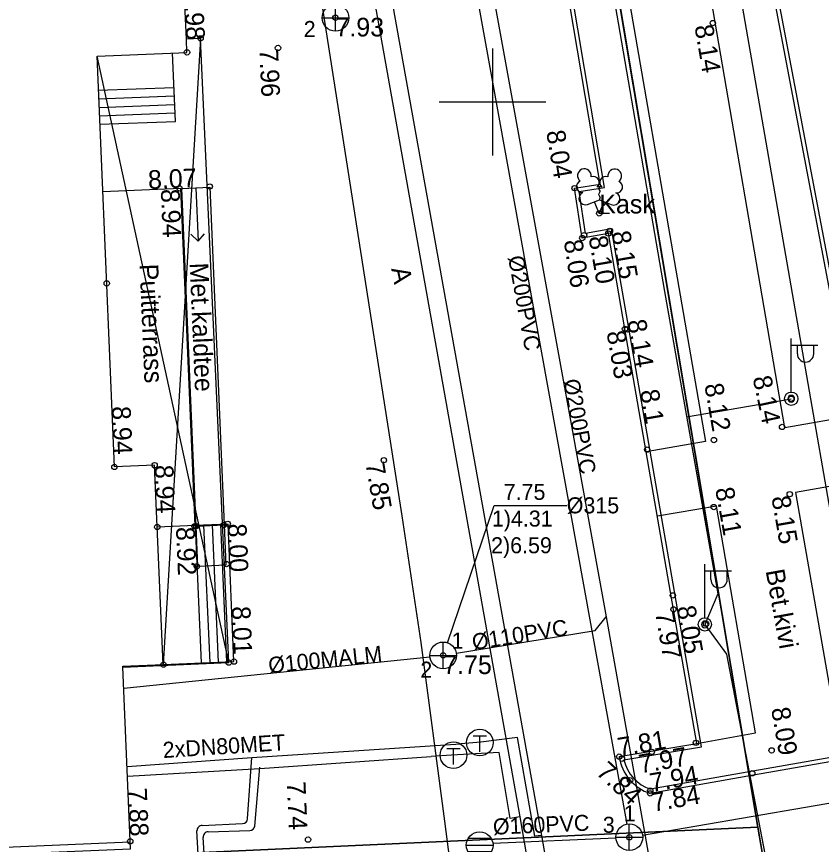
# Model space of a CAD drawing. Extents: x 473307 to 473719, y 6532843 to 6533381.
# Drawn here: x 473582.18 to 473612.32, y 6533222.19 to 6533253.2 of the extents above; entities that cross this region are included whole.
import ezdxf

# ---------------------------------------------------------------- set-up
doc = ezdxf.new("R2010")
doc.units = 0
for name, color, linetype in [('Default', 7, 'Continuous'), ('HOONE', 7, 'Continuous'), ('HOONEDET', 7, 'Continuous'), ('KKAEV', 7, 'Continuous'), ('KKAEV_NR', 7, 'Continuous'), ('KORGUS', 7, 'Continuous'), ('KPKAABEL', 7, 'Continuous'), ('KTRASS', 7, 'Continuous'), ('KTRASS_TEKST', 7, 'Continuous'), ('MPKAABEL', 7, 'Continuous'), ('PIIR', 7, 'Continuous'), ('POST', 7, 'Continuous'), ('PUU', 7, 'Continuous'), ('SITRASS', 7, 'Continuous'), ('SKKAEV', 7, 'Continuous'), ('SKKAEV_NR', 7, 'Continuous'), ('SKTRASS', 7, 'Continuous'), ('SKTRASS_TEKST', 7, 'Continuous'), ('TEE', 7, 'Continuous'), ('TKAEV', 7, 'Continuous'), ('TTRASS', 7, 'Continuous'), ('TTRASS_TEKST', 7, 'Continuous'), ('VORK', 7, 'Continuous')]:
    doc.layers.add(name, color=color, linetype=linetype)

# ---------------------------------------------------------------- blocks, each defined once
blk = doc.blocks.new('KAKAEV')
at = {"layer": 'Default'}
for p, q in [((0, -1), (0, 1)), ((-1, 0), (1, 0))]:
    blk.add_line(p, q, dxfattribs=at)
blk.add_circle((0, 0), 1, dxfattribs=at)
blk = doc.blocks.new('REKAEV')
at = {"layer": 'Default'}
for p, q in [((-1, 0), (1, 0)), ((0.86, 0.5), (-0.86, 0.5)), ((0.86, -0.5), (-0.86, -0.5))]:
    blk.add_line(p, q, dxfattribs=at)
blk.add_circle((0, 0), 1, dxfattribs=at)
blk = doc.blocks.new('LEHTP2')
at = {"layer": 'Default'}
for p, q in [((-0.88, 0.67), (0.01, 1.02)), ((0, 0), (-0.35, 0.88)), ((0, 0), (0.36, 0.88)), ((0.01, 1.02), (0.89, 0.66)), ((0.76, 0), (0, 0))]:
    blk.add_line(p, q, dxfattribs=at)
blk.add_lwpolyline([(0.01, 2.01), (-0.03, 1.86), (-0.03, 1.82), (-0.01, 1.76), (0.03, 1.69), (0.04, 1.65), (0.01, 1.58), (-0.04, 1.48), (-0.05, 1.43), (-0.04, 1.4), (-0.02, 1.34), (0.05, 1.22), (0.06, 1.18), (0.05, 1.14), (0.02, 1.07), (0.01, 1.02)], dxfattribs=at)
for centre, radius, start, end in [((-1.114, 2.828), 0.512, 111.50269, 232.51731), ((-1.114, 2.828), 0.512, 350.48556, 111.50017), ((1.158, 2.811), 0.512, 67.6168, 188.63142), ((1.158, 2.811), 0.512, 306.59966, 67.61428), ((-0.445, 2.327), 0.448, 308.50412, 111.57247), ((0.481, 2.318), 0.45, 67.7016, 230.51262), ((-1.262, 2.005), 0.448, 111.43041, 274.49868), ((0.008, 1.535), 0.475, 66.76552, 111.50149), ((1.293, 1.986), 0.448, 264.6183, 67.68657), ((-1.053, 1.117), 0.475, 111.50143, 291.50036), ((1.07, 1.101), 0.475, 247.61661, 67.61554)]:
    blk.add_arc(centre, radius, start, end, dxfattribs=at)
blk = doc.blocks.new('MEPOST')
at = {"layer": 'Default'}
blk.add_circle((0, 0), 0.5, dxfattribs=at)
for start, end in [(0, 180), (180, 0)]:
    blk.add_arc((0, 0), 0.25, start, end, dxfattribs=at)
blk = doc.blocks.new('VAPOST')
at = {"layer": 'Default'}
for p, q in [((0, 0.5), (0, 4.5)), ((0, 4), (2, 4)), ((0.453, 3.358), (0.453, 4)), ((1.679, 3.358), (1.679, 4))]:
    blk.add_line(p, q, dxfattribs=at)
blk.add_arc((1.066, 3.358), 0.613, 180, 0, dxfattribs=at)
blk = doc.blocks.new('SOKAEV')
at = {"layer": 'Default'}
for p, q in [((-0.5, 0.5), (0.5, 0.5)), ((0, -0.7), (0, 0.5))]:
    blk.add_line(p, q, dxfattribs=at)
blk.add_circle((0, 0), 1, dxfattribs=at)
blk = doc.blocks.new('VKORIS')
at = {"layer": 'Default'}
for p, q in [((0, 4), (0, -4)), ((-4, 0), (4, 0))]:
    blk.add_line(p, q, dxfattribs=at)

msp = doc.modelspace()

# ---------------------------------------------------------------- linework, layer by layer
at = {"layer": 'HOONE'}
for points in [[(473586.451, 6533222.028), (473586.163, 6533228.83), (473590.126, 6533228.998), (473589.07, 6533252.381), (473588.538, 6533252.355), (473587.928, 6533265.086), (473574.864, 6533264.513), (473574.621, 6533270.17), (473553.465, 6533269.148), (473553.468, 6533269.088), (473497.143, 6533266.366), (473498.091, 6533246.719), (473499.996, 6533208.142), (473556.654, 6533210.892), (473555.213, 6533238.366), (473566.97, 6533238.94), (473567.826, 6533221.491), (473567.7, 6533221.486), (473567.712, 6533221.234), (473586.451, 6533222.028)], [(473586.163, 6533228.83), (473586.161, 6533228.861), (473587.666, 6533228.924), (473587.35, 6533236.393), (473585.845, 6533236.33), (473585.193, 6533251.717), (473588.562, 6533251.859), (473588.538, 6533252.355)]]:
    msp.add_lwpolyline(points, dxfattribs=at)
at = {"layer": 'HOONEDET'}
for p, q in [((473585.247, 6533250.436), (473588.072, 6533250.546)), ((473585.26, 6533250.118), (473588.085, 6533250.228)), ((473585.272, 6533249.799), (473588.097, 6533249.91)), ((473585.285, 6533249.481), (473588.11, 6533249.592)), ((473588.891, 6533246.787), (473588.976, 6533244.781)), ((473588.976, 6533244.781), (473588.706, 6533245.043)), ((473588.976, 6533244.781), (473589.223, 6533245.065)), ((473588.905, 6533234.111), (473589.95, 6533234.155)), ((473589.183, 6533234.151), (473589.412, 6533228.998)), ((473589.499, 6533234.164), (473589.728, 6533229.011)), ((473589.814, 6533234.178), (473590.043, 6533229.025)), ((473588.868, 6533234.138), (473589.097, 6533228.985)), ((473567.826, 6533221.491), (473586.44, 6533222.28))]:
    msp.add_line(p, q, dxfattribs=at)
for points in [[(473589.07, 6533252.381), (473587.666, 6533228.924)], [(473585.301, 6533249.163), (473588.126, 6533249.274), (473588.018, 6533251.836)], [(473590.126, 6533228.998), (473585.193, 6533251.717)], [(473588.868, 6533234.138), (473588.333, 6533246.763), (473585.408, 6533246.639)], [(473588.369, 6533246.764), (473589.414, 6533246.809), (473589.95, 6533234.155), (473590.013, 6533232.649), (473588.969, 6533232.605), (473588.905, 6533234.111), (473588.369, 6533246.764)], [(473587.666, 6533228.924), (473590.322, 6533229.036), (473590.104, 6533234.19), (473588.868, 6533234.138), (473587.448, 6533234.078)]]:
    msp.add_lwpolyline(points, dxfattribs=at)
at = {"layer": 'KKAEV_NR'}
msp.add_lwpolyline([(473598.317, 6533229.744), (473600.062, 6533234.89), (473602.783, 6533234.89)], dxfattribs=at)
at = {"layer": 'KORGUS'}
for centre in [(473594.121, 6533253.154), (473608.254, 6533252.957), (473589.07, 6533252.381), (473588.562, 6533251.859), (473591.97, 6533252.023), (473588.28, 6533246.761), (473589.413, 6533246.834), (473603.078, 6533246.77), (473604.002, 6533245.825), (473603.363, 6533244.901), (473603.434, 6533245.011), (473604.341, 6533245.074), (473604.4, 6533245.173), (473585.554, 6533243.205), (473604.961, 6533241.496), (473605.041, 6533241.48), (473611.192, 6533238.885), (473610.847, 6533237.827), (473608.293, 6533237.337), (473605.794, 6533236.978), (473595.933, 6533236.582), (473585.845, 6533236.33), (473587.35, 6533236.393), (473611.136, 6533235.31), (473608.289, 6533234.825), (473587.448, 6533234.078), (473588.848, 6533234.1), (473588.905, 6533234.109), (473589.939, 6533234.155), (473590.089, 6533234.196), (473588.931, 6533232.603), (473590.044, 6533232.689), (473606.757, 6533231.515), (473606.781, 6533230.992), (473607.999, 6533230.452), (473598.156, 6533229.27), (473587.683, 6533228.925), (473590.126, 6533228.998), (473590.322, 6533229.036), (473607.62, 6533225.995), (473610.457, 6533225.711), (473604.75, 6533225.478), (473604.85, 6533225.397), (473605.971, 6533225.655), (473609.729, 6533224.853), (473605.155, 6533224.589), (473605.912, 6533224.206), (473605.907, 6533224.098), (473586.438, 6533222.308), (473593.094, 6533222.367), (473605.127, 6533222.457)]:
    msp.add_circle(centre, 0.1, dxfattribs=at)
at = {"layer": 'KPKAABEL'}
msp.add_lwpolyline([(473599.245, 6533215.151), (473598.214, 6533223.062), (473597.334, 6533229.753), (473596.618, 6533234.501), (473594.535, 6533247.835), (473592.795, 6533258.945), (473591.16, 6533268.89), (473578.283, 6533269.448)], dxfattribs=at)
at = {"layer": 'KTRASS'}
for points in [[(473596.379, 6533274.552), (473599.595, 6533256.427), (473604.261, 6533230.713), (473605.956, 6533221.161)], [(473598.649, 6533229.351), (473603.845, 6533230.204), (473604.259, 6533230.711)], [(473586.196, 6533228.038), (473597.659, 6533229.219)]]:
    msp.add_lwpolyline(points, dxfattribs=at)
at = {"layer": 'MPKAABEL'}
for points in [[(473525.948, 6533290.824), (473539.287, 6533291.718), (473545.145, 6533292.046), (473550.656, 6533292.727), (473564.851, 6533292.918), (473566.45, 6533292.671), (473568.205, 6533285.94), (473572.537, 6533278.089), (473573.477, 6533277.469), (473574.937, 6533277.378), (473588.904, 6533277.934), (473598.263, 6533278.206), (473600.541, 6533275.557), (473602.095, 6533267.853), (473603.802, 6533258.2), (473603.216, 6533257.059), (473604.096, 6533256.527), (473606.448, 6533242.906), (473608.439, 6533231.57), (473607.954, 6533230.431), (473608.769, 6533229.316), (473610.682, 6533219.295)], [(473603.216, 6533257.059), (473604.096, 6533256.527), (473606.448, 6533242.906), (473608.439, 6533231.57), (473607.954, 6533230.431)], [(473607.273, 6533238.211), (473611.192, 6533238.885)], [(473607.954, 6533230.431), (473608.769, 6533229.316), (473610.682, 6533219.295), (473613.1, 6533204.928), (473612.486, 6533203.753)]]:
    msp.add_lwpolyline(points, dxfattribs=at)
at = {"layer": 'PIIR'}
msp.add_lwpolyline([(473678.608, 6532842.593), (473677.66, 6532847.73), (473668.24, 6532906.4), (473664.64, 6532927.81), (473654.16, 6532926.37), (473630.89, 6533065.72), (473641.36, 6533067.51), (473636.3, 6533097.55), (473618.8, 6533170.64), (473609.94, 6533222.84), (473601.54, 6533272.81), (473599.09, 6533295.91), (473592.3, 6533328.43), (473587.14, 6533353.72), (473584.47, 6533353.28), (473580.56, 6533374.06), (473585.23, 6533374.14), (473584.699, 6533380.885)], dxfattribs=at)
for points in [[(473586.5, 6533271.93), (473601.56, 6533272.81), (473609.94, 6533222.84), (473586.39, 6533221.76), (473567.96, 6533221.17), (473565.61, 6533263.9), (473587.68, 6533264.9)], [(473558.63, 6533220.73), (473567.96, 6533221.17), (473586.39, 6533221.76), (473609.94, 6533222.84), (473618.8, 6533170.64), (473601.75, 6533167.04), (473561.43, 6533165.2), (473559.2, 6533209.37)]]:
    msp.add_lwpolyline(points, close=True, dxfattribs=at)
at = {"layer": 'SITRASS'}
msp.add_lwpolyline([(473619.598, 6533194.755), (473606.651, 6533269.171)], dxfattribs=at)
at = {"layer": 'SKKAEV_NR'}
msp.add_lwpolyline([(473605.62, 6533222.541), (473615.79, 6533224.289), (473619.645, 6533224.289)], dxfattribs=at)
at = {"layer": 'SKTRASS'}
msp.add_line((473595.936, 6533273.237), (473605.038, 6533222.949), dxfattribs=at)
msp.add_lwpolyline([(473600.016, 6533222.238), (473604.627, 6533222.435)], dxfattribs=at)
at = {"layer": 'TEE'}
for points in [[(473606.081, 6533277.468), (473606.665, 6533274.345), (473613.506, 6533238.237), (473615.579, 6533226.633)], [(473606.226, 6533277.506), (473606.812, 6533274.373), (473613.654, 6533238.264), (473613.654, 6533238.264), (473615.735, 6533226.614)], [(473592.376, 6533275.568), (473601.305, 6533275.875), (473607.974, 6533237.28), (473605.758, 6533236.896)], [(473604.75, 6533225.478), (473607.651, 6533225.971), (473606.781, 6533230.992), (473605.758, 6533236.896), (473604.961, 6533241.496), (473604.341, 6533245.074), (473603.363, 6533244.901), (473603.078, 6533246.77), (473604.03, 6533246.923), (473602.054, 6533258.671), (473599.216, 6533274.876), (473594.157, 6533274.026)], [(473604.925, 6533225.356), (473607.824, 6533225.848), (473606.929, 6533231.017), (473605.906, 6533236.922), (473605.109, 6533241.522), (473604.463, 6533245.248), (473603.488, 6533245.076), (473603.249, 6533246.645), (473604.203, 6533246.799), (473602.202, 6533258.697), (473599.338, 6533275.049), (473594.198, 6533274.185)], [(473613.654, 6533238.264), (473610.95, 6533237.796), (473604.734, 6533274.019), (473606.812, 6533274.373)], [(473614.114, 6533235.854), (473611.354, 6533235.374), (473613.096, 6533225.365)], [(473607.651, 6533225.971), (473609.854, 6533226.364), (473608.387, 6533234.862), (473606.177, 6533234.479)], [(473614.666, 6533225.79), (473609.751, 6533224.935), (473605.918, 6533224.253)], [(473614.705, 6533225.644), (473609.777, 6533224.788), (473605.907, 6533224.098)]]:
    msp.add_lwpolyline(points, dxfattribs=at)
for radius, start, end in [(1.683, 187.6541, 252.3154), (1.533, 193.0666, 250.9597)]:
    msp.add_arc((473606.419, 6533225.702), radius, start, end, dxfattribs=at)
at = {"layer": 'TTRASS'}
for points in [[(473592.297, 6533277.757), (473596.188, 6533254.087), (473601.84, 6533222.521), (473604, 6533210.082), (473607.02, 6533191.72), (473607.264, 6533190.194), (473603.552, 6533189.561), (473604.136, 6533186.261), (473607.868, 6533186.888), (473612.623, 6533162.34), (473616.873, 6533138.735), (473619.773, 6533121.514), (473620.151, 6533119.324)], [(473591.775, 6533277.426), (473595.59, 6533253.766), (473601.028, 6533223.219), (473603.147, 6533210.812), (473606.172, 6533192.662), (473606.51, 6533190.705), (473602.77, 6533190.028), (473603.588, 6533185.543), (473607.3, 6533186.208), (473612.067, 6533161.644), (473616.282, 6533137.983), (473619.426, 6533120.252), (473619.546, 6533119.497)], [(473601.84, 6533222.521), (473601.582, 6533222.494), (473600.936, 6533226.191), (473599.567, 6533226.024), (473598.821, 6533225.952)], [(473586.32, 6533225.105), (473590.994, 6533225.444), (473598.821, 6533225.952)], [(473586.335, 6533224.75), (473591.284, 6533225.034), (473597.702, 6533225.482)], [(473601.028, 6533223.219), (473600.663, 6533223.154), (473600.251, 6533225.628), (473598.469, 6533225.529), (473597.702, 6533225.482)], [(473590.834, 6533223.144), (473590.994, 6533225.444)], [(473591.104, 6533222.874), (473591.288, 6533225.083)], [(473589.32, 6533215.907), (473588.935, 6533222.692)], [(473589.127, 6533222.903), (473590.645, 6533222.967)], [(473589.36, 6533222.661), (473590.915, 6533222.709)], [(473589.576, 6533215.918), (473589.166, 6533222.448)]]:
    msp.add_lwpolyline(points, dxfattribs=at)
for centre, radius, start, end in [((473590.636, 6533223.165), 0.199, 272.4189, 353.9184), ((473589.135, 6533222.703), 0.2, 92.4109, 183.2493), ((473590.909, 6533222.907), 0.198, 271.7859, 350.5142), ((473589.366, 6533222.461), 0.2, 91.7727, 183.5911)]:
    msp.add_arc(centre, radius, start, end, dxfattribs=at)

# ---------------------------------------------------------------- block references
at = {"layer": 'KKAEV', "xscale": 0.5, "yscale": 0.5}
for p in [(473594.121, 6533253.154), (473598.156, 6533229.27)]:
    msp.add_blockref('KAKAEV', p, dxfattribs=at)
at = {"layer": 'POST', "xscale": 0.5, "yscale": 0.5}
for name, p in [('VAPOST', (473611.192, 6533238.885)), ('MEPOST', (473611.192, 6533238.885)), ('VAPOST', (473607.954, 6533230.431)), ('MEPOST', (473607.954, 6533230.431))]:
    msp.add_blockref(name, p, dxfattribs=at)
at = {"layer": 'PUU', "xscale": 0.5, "yscale": 0.5}
msp.add_blockref('LEHTP2', (473604.002, 6533245.825), dxfattribs=at)
at = {"layer": 'SKKAEV', "xscale": 0.5, "yscale": 0.5}
for name, p in [('KAKAEV', (473605.127, 6533222.457)), ('REKAEV', (473599.522, 6533222.157))]:
    msp.add_blockref(name, p, dxfattribs=at)
at = {"layer": 'TKAEV', "xscale": 0.5, "yscale": 0.5}
for p in [(473599.529, 6533226.003), (473598.54, 6533225.531)]:
    msp.add_blockref('SOKAEV', p, dxfattribs=at)
at = {"layer": 'VORK', "xscale": 0.5, "yscale": 0.5}
msp.add_blockref('VKORIS', (473600, 6533250), dxfattribs=at)

# ---------------------------------------------------------------- texts
at = {"layer": 'HOONE'}
for s, p in [('Puitterrass', (473586.785, 6533243.923)), ('Met.kaldtee', (473588.661, 6533243.967))]:
    msp.add_text(s, height=0.7, rotation=272.4254, dxfattribs=at).set_placement(p)
at = {"layer": 'KKAEV_NR'}
for s, p in [('2', (473592.933, 6533252.433)), ('7.75', (473600.423, 6533235.095)), ('%%c315', (473602.783, 6533234.59)), ('1)4.31', (473599.98, 6533234.095)), ('2)6.59', (473599.951, 6533233.095)), ('1', (473598.47, 6533229.523)), ('2', (473597.3, 6533228.434))]:
    msp.add_text(s, height=0.6, dxfattribs=at).set_placement(p)
at = {"layer": 'KORGUS'}
for s, rotation, p in [('7.98', 272.7226, (473588.454, 6533254.123)), ('8.14', 279.7205, (473607.564, 6533252.839)), ('7.96', 272.585, (473591.271, 6533251.991)), ('8.04', 279.5495, (473602.012, 6533248.889)), ('8.07', 2.4254, (473587.115, 6533246.737)), ('8.94', 272.4254, (473587.581, 6533246.731)), ('8.15', 279.8271, (473604.46, 6533245.115)), ('8.06', 278.6564, (473602.671, 6533244.796)), ('8.10', 279.8271, (473603.599, 6533244.935)), ('8.14', 279.8271, (473605.05, 6533241.799)), ('8.03', 279.8271, (473604.271, 6533241.377)), ('8.14', 281.9231, (473609.742, 6533239.672)), ('8.12', 279.8029, (473607.936, 6533239.407)), ('8.1', 279.828, (473605.528, 6533239.177)), ('8.94', 272.4254, (473585.749, 6533238.594)), ('8.94', 272.4254, (473587.35, 6533236.393)), ('7.85', 279.828, (473595.243, 6533236.463)), ('8.11', 280.2148, (473608.339, 6533235.509)), ('8.15', 279.8731, (473610.446, 6533235.19)), ('8.00', 272.4254, (473590.089, 6533234.196)), ('8.92', 272.4254, (473588.149, 6533234.07)), ('8.01', 272.4254, (473590.235, 6533231.101)), ('8.05', 279.828, (473606.901, 6533231.077)), ('7.97', 279.828, (473606.091, 6533230.872)), ('8.09', 279.7964, (473610.435, 6533227.272)), ('7.81', 9.6419, (473604.75, 6533225.478)), ('7.97', 9.6419, (473605.542, 6533224.848)), ('7.84', 317.2178, (473603.848, 6533224.845)), ('7.94', 10.098, (473605.959, 6533224.147)), ('7.88', 272.4259, (473586.355, 6533224.293)), ('7.74', 272.5441, (473592.297, 6533224.534)), ('7.84', 10.098, (473606.03, 6533223.409))]:
    msp.add_text(s, height=0.7, rotation=rotation, dxfattribs=at).set_placement(p)
for s, p in [('7.93', (473594.121, 6533252.454)), ('7.75', (473598.156, 6533228.57))]:
    msp.add_text(s, height=0.7, dxfattribs=at).set_placement(p)
at = {"layer": 'KTRASS_TEKST'}
for s, rotation, p in [('%%c200PVC', 280.283, (473602.654, 6533239.572)), ('%%c110PVC', 9.0783, (473599.286, 6533229.464)), ('%%c100MALM', 6.0009, (473591.638, 6533228.594))]:
    msp.add_text(s, height=0.6, rotation=rotation, dxfattribs=at).set_placement(p)
at = {"layer": 'PUU'}
msp.add_text('Kask', height=0.7, dxfattribs=at).set_placement((473604.002, 6533245.825))
at = {"layer": 'SKKAEV_NR'}
for s, p in [('1', (473604.914, 6533223.05)), ('3', (473604.133, 6533222.624))]:
    msp.add_text(s, height=0.6, dxfattribs=at).set_placement(p)
at = {"layer": 'SKTRASS_TEKST'}
for s, rotation, p in [('%%c200PVC', 280.2932, (473600.582, 6533244.192)), ('%%c160PVC', 2.4554, (473600.032, 6533222.552))]:
    msp.add_text(s, height=0.6, rotation=rotation, dxfattribs=at).set_placement(p)
at = {"layer": 'TEE'}
for s, rotation, p in [('A', 281.3978, (473596.205, 6533243.754)), ('Bet.kivi', 280.2189, (473610.229, 6533232.44))]:
    msp.add_text(s, height=0.7, rotation=rotation, dxfattribs=at).set_placement(p)
at = {"layer": 'TTRASS_TEKST'}
msp.add_text('2xDN80MET', height=0.6, rotation=3.7172, dxfattribs=at).set_placement((473587.674, 6533225.423))

doc.saveas('drawing.dxf')
